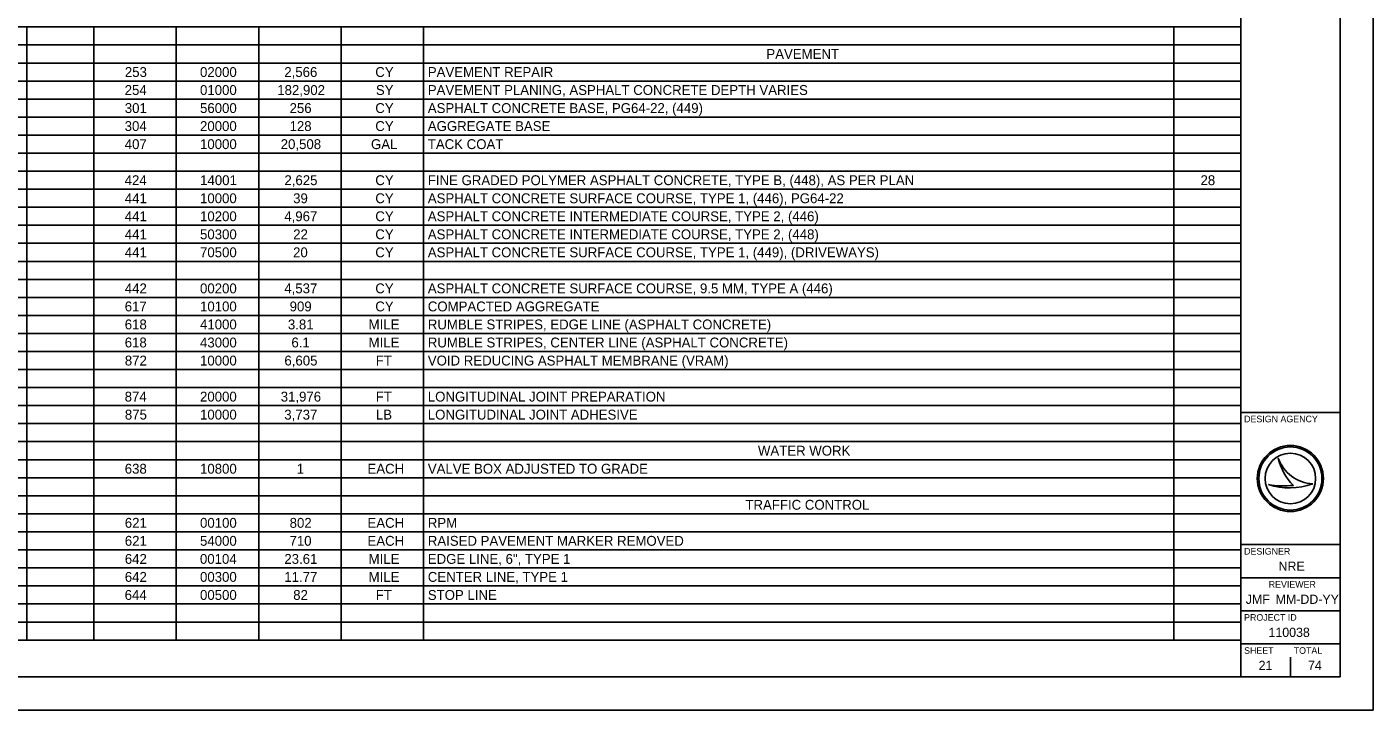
# Model space of a CAD drawing. Extents: x 0 to 34, y 0 to 22.
# Drawn here: x 13.65 to 34, y 0 to 10.33 of the extents above; entities that cross this region are included whole.
import ezdxf

# ---------------------------------------------------------------- set-up
doc = ezdxf.new("R2010")
doc.units = 0
for name, color, linetype in [('Default', 7, 'Continuous'), ('SH_Border', 7, 'Continuous'), ('SH_Cut_Line', 7, 'Continuous'), ('SH_Data', 7, 'Continuous')]:
    doc.layers.add(name, color=color, linetype=linetype)

msp = doc.modelspace()

# ---------------------------------------------------------------- linework, layer by layer
at = {"layer": 'Default'}
for p, q in [((12.636, 10.325), (13.648, 10.325)), ((13.648, 10.325), (32, 10.325)), ((13.648, 10.325), (13.648, 10.053)), ((14.66, 10.325), (14.66, 10.053)), ((15.906, 10.325), (15.906, 10.053)), ((17.152, 10.325), (17.152, 10.053)), ((18.398, 10.325), (18.398, 10.053)), ((19.644, 10.325), (19.644, 10.053)), ((30.988, 10.325), (30.988, 10.053)), ((32, 10.325), (32, 10.053)), ((12.636, 10.053), (13.648, 10.053)), ((13.648, 10.053), (32, 10.053)), ((13.648, 10.053), (13.648, 9.235)), ((14.66, 10.053), (14.66, 9.235)), ((15.906, 10.053), (15.906, 9.235)), ((17.152, 10.053), (17.152, 9.235)), ((18.398, 10.053), (18.398, 9.235)), ((19.644, 10.053), (19.644, 9.235)), ((30.988, 10.053), (30.988, 9.235)), ((32, 10.053), (32, 9.235)), ((12.636, 9.78), (13.648, 9.78)), ((13.648, 9.78), (32, 9.78)), ((12.636, 9.508), (13.648, 9.508)), ((13.648, 9.508), (32, 9.508)), ((12.636, 9.235), (13.648, 9.235)), ((13.648, 9.235), (32, 9.235)), ((13.648, 9.235), (13.648, 8.69)), ((14.66, 9.235), (14.66, 8.69)), ((15.906, 9.235), (15.906, 8.69)), ((17.152, 9.235), (17.152, 8.69)), ((18.398, 9.235), (18.398, 8.69)), ((19.644, 9.235), (19.644, 8.69)), ((30.988, 9.235), (30.988, 8.69)), ((32, 9.235), (32, 8.69)), ((12.636, 8.963), (13.648, 8.963)), ((13.648, 8.963), (32, 8.963)), ((12.636, 8.69), (13.648, 8.69)), ((13.648, 8.69), (32, 8.69)), ((13.648, 8.69), (13.648, 7.872)), ((14.66, 8.69), (14.66, 7.872)), ((15.906, 8.69), (15.906, 7.872)), ((17.152, 8.69), (17.152, 7.872)), ((18.398, 8.69), (18.398, 7.872)), ((19.644, 8.69), (19.644, 7.872)), ((30.988, 8.69), (30.988, 7.872)), ((32, 8.69), (32, 7.872)), ((12.636, 8.417), (13.648, 8.417)), ((13.648, 8.417), (32, 8.417)), ((12.636, 8.145), (13.648, 8.145)), ((13.648, 8.145), (32, 8.145)), ((12.636, 7.872), (13.648, 7.872)), ((13.648, 7.872), (32, 7.872)), ((13.648, 7.872), (13.648, 7.327)), ((14.66, 7.872), (14.66, 7.327)), ((15.906, 7.872), (15.906, 7.327)), ((17.152, 7.872), (17.152, 7.327)), ((18.398, 7.872), (18.398, 7.327)), ((19.644, 7.872), (19.644, 7.327)), ((30.988, 7.872), (30.988, 7.327)), ((32, 7.872), (32, 7.327)), ((12.636, 7.6), (13.648, 7.6)), ((13.648, 7.6), (32, 7.6)), ((12.636, 7.327), (13.648, 7.327)), ((13.648, 7.327), (32, 7.327)), ((13.648, 7.327), (13.648, 6.51)), ((14.66, 7.327), (14.66, 6.51)), ((15.906, 7.327), (15.906, 6.51)), ((17.152, 7.327), (17.152, 6.51)), ((18.398, 7.327), (18.398, 6.51)), ((19.644, 7.327), (19.644, 6.51)), ((30.988, 7.327), (30.988, 6.51)), ((32, 7.327), (32, 6.51)), ((12.636, 7.055), (13.648, 7.055)), ((13.648, 7.055), (32, 7.055)), ((12.636, 6.782), (13.648, 6.782)), ((13.648, 6.782), (32, 6.782)), ((12.636, 6.51), (13.648, 6.51)), ((13.648, 6.51), (32, 6.51)), ((13.648, 6.51), (13.648, 5.419)), ((14.66, 6.51), (14.66, 5.419)), ((15.906, 6.51), (15.906, 5.419)), ((17.152, 6.51), (17.152, 5.419)), ((18.398, 6.51), (18.398, 5.419)), ((19.644, 6.51), (19.644, 5.419)), ((30.988, 6.51), (30.988, 5.419)), ((32, 6.51), (32, 5.419)), ((12.636, 6.237), (13.648, 6.237)), ((13.648, 6.237), (32, 6.237)), ((12.636, 5.964), (13.648, 5.964)), ((13.648, 5.964), (32, 5.964)), ((12.636, 5.692), (13.648, 5.692)), ((13.648, 5.692), (32, 5.692)), ((12.636, 5.419), (13.648, 5.419)), ((13.648, 5.419), (32, 5.419)), ((13.648, 5.419), (13.648, 5.147)), ((14.66, 5.419), (14.66, 5.147)), ((15.906, 5.419), (15.906, 5.147)), ((17.152, 5.419), (17.152, 5.147)), ((18.398, 5.419), (18.398, 5.147)), ((19.644, 5.419), (19.644, 5.147)), ((30.988, 5.419), (30.988, 5.147)), ((32, 5.419), (32, 5.147)), ((12.636, 5.147), (13.648, 5.147)), ((13.648, 5.147), (32, 5.147)), ((13.648, 5.147), (13.648, 4.057)), ((14.66, 5.147), (14.66, 4.057)), ((15.906, 5.147), (15.906, 4.057)), ((17.152, 5.147), (17.152, 4.057)), ((18.398, 5.147), (18.398, 4.057)), ((19.644, 5.147), (19.644, 4.057)), ((30.988, 5.147), (30.988, 4.057)), ((32, 5.147), (32, 4.057)), ((12.636, 4.874), (13.648, 4.874)), ((13.648, 4.874), (32, 4.874)), ((12.636, 4.602), (13.648, 4.602)), ((13.648, 4.602), (32, 4.602)), ((12.636, 4.329), (13.648, 4.329)), ((13.648, 4.329), (32, 4.329)), ((12.636, 4.057), (13.648, 4.057)), ((13.648, 4.057), (32, 4.057)), ((13.648, 4.057), (13.648, 3.784)), ((14.66, 4.057), (14.66, 3.784)), ((15.906, 4.057), (15.906, 3.784)), ((17.152, 4.057), (17.152, 3.784)), ((18.398, 4.057), (18.398, 3.784)), ((19.644, 4.057), (19.644, 3.784)), ((30.988, 4.057), (30.988, 3.784)), ((32, 4.057), (32, 3.784)), ((12.636, 3.784), (13.648, 3.784)), ((13.648, 3.784), (32, 3.784)), ((13.648, 3.784), (13.648, 2.694)), ((14.66, 3.784), (14.66, 2.694)), ((15.906, 3.784), (15.906, 2.694)), ((17.152, 3.784), (17.152, 2.694)), ((18.398, 3.784), (18.398, 2.694)), ((19.644, 3.784), (19.644, 2.694)), ((30.988, 3.784), (30.988, 2.694)), ((32, 3.784), (32, 2.694)), ((12.636, 3.511), (13.648, 3.511)), ((13.648, 3.511), (32, 3.511)), ((12.636, 3.239), (13.648, 3.239)), ((13.648, 3.239), (32, 3.239)), ((12.636, 2.966), (13.648, 2.966)), ((13.648, 2.966), (32, 2.966)), ((12.636, 2.694), (13.648, 2.694)), ((13.648, 2.694), (32, 2.694)), ((13.648, 2.694), (13.648, 2.421)), ((14.66, 2.694), (14.66, 2.421)), ((15.906, 2.694), (15.906, 2.421)), ((17.152, 2.694), (17.152, 2.421)), ((18.398, 2.694), (18.398, 2.421)), ((19.644, 2.694), (19.644, 2.421)), ((30.988, 2.694), (30.988, 2.421)), ((32, 2.694), (32, 2.421)), ((12.636, 2.421), (13.648, 2.421)), ((13.648, 2.421), (32, 2.421)), ((13.648, 2.421), (13.648, 1.331)), ((14.66, 2.421), (14.66, 1.331)), ((15.906, 2.421), (15.906, 1.331)), ((17.152, 2.421), (17.152, 1.331)), ((18.398, 2.421), (18.398, 1.331)), ((19.644, 2.421), (19.644, 1.331)), ((30.988, 2.421), (30.988, 1.331)), ((32, 2.421), (32, 1.331)), ((12.636, 2.149), (13.648, 2.149)), ((13.648, 2.149), (32, 2.149)), ((12.636, 1.876), (13.648, 1.876)), ((13.648, 1.876), (32, 1.876)), ((12.636, 1.604), (13.648, 1.604)), ((13.648, 1.604), (32, 1.604)), ((12.636, 1.331), (13.648, 1.331)), ((13.648, 1.331), (32, 1.331)), ((13.648, 1.331), (13.648, 1.059)), ((14.66, 1.331), (14.66, 1.059)), ((15.906, 1.331), (15.906, 1.059)), ((17.152, 1.331), (17.152, 1.059)), ((18.398, 1.331), (18.398, 1.059)), ((19.644, 1.331), (19.644, 1.059)), ((30.988, 1.331), (30.988, 1.059)), ((32, 1.331), (32, 1.059)), ((12.636, 1.059), (13.648, 1.059)), ((13.648, 1.059), (32, 1.059))]:
    msp.add_line(p, q, dxfattribs=at)
at = {"layer": 'SH_Border'}
for p, q in [((32, 0.5), (32, 21.5)), ((32, 4.5), (33.5, 4.5)), ((32, 2.5), (33.5, 2.5)), ((32, 2), (33.5, 2)), ((32, 1.5), (33.5, 1.5)), ((32, 1), (33.5, 1))]:
    msp.add_line(p, q, dxfattribs=at)
msp.add_lwpolyline([(1.5, 21.5), (33.5, 21.5), (33.5, 0.5), (1.5, 0.5)], close=True, dxfattribs=at)
at = {"layer": 'SH_Cut_Line'}
msp.add_lwpolyline([(0, 0), (34, 0), (34, 22), (0, 22)], close=True, dxfattribs=at)
at = {"layer": 'SH_Data'}
for p, q in [((32.567, 3.81), (32.567, 3.81)), ((32.75, 3.5), (32.75, 3.5)), ((32.417, 3.41), (32.417, 3.41)), ((33.087, 3.419), (33.087, 3.419)), ((32.375, 0.675), (32.375, 0.675)), ((32.75, 0.5), (32.75, 0.8))]:
    msp.add_line(p, q, dxfattribs=at)
for radius in [0.5, 0.477, 0.477, 0.382]:
    msp.add_circle((32.75, 3.5), radius, dxfattribs=at)
for centre, radius, start, end in [((33.116, 3.998), 0.58, 198.9257, 198.9319), ((33.347, 3.97), 0.796, 191.6379, 191.6421), ((33.116, 3.998), 0.58, 198.9319, 267.1657), ((33.347, 3.97), 0.796, 191.6421, 226.0947), ((32.739, 4.37), 1.013, 251.4576, 290.0832), ((32.648, 4.654), 1.266, 259.4964, 259.4995), ((32.739, 4.37), 1.013, 251.4527, 251.4576), ((32.648, 4.654), 1.266, 259.4995, 276.6672)]:
    msp.add_arc(centre, radius, start, end, dxfattribs=at)

# ---------------------------------------------------------------- texts
at = {"layer": 'Default'}
for s, height, p in [('PAVEMENT', 0.1493, (24.828, 9.842)), ('253', 0.1493, (15.129, 9.569)), ('02000', 0.1493, (16.265, 9.569)), ('2,566', 0.1493, (17.539, 9.569)), ('CY', 0.1493, (18.915, 9.569)), ('PAVEMENT REPAIR', 0.14926, (19.709, 9.569)), ('254', 0.1493, (15.126, 9.297)), ('01000', 0.1493, (16.265, 9.297)), ('182,902', 0.1493, (17.433, 9.297)), ('SY', 0.1493, (18.924, 9.297)), ('PAVEMENT PLANING, ASPHALT CONCRETE DEPTH VARIES', 0.14926, (19.709, 9.297)), ('301', 0.1493, (15.128, 9.024)), ('56000', 0.1493, (16.265, 9.024)), ('256', 0.1493, (17.619, 9.024)), ('CY', 0.1493, (18.915, 9.024)), ('ASPHALT CONCRETE BASE, PG64-22, (449)', 0.14926, (19.709, 9.024)), ('304', 0.1493, (15.126, 8.752)), ('20000', 0.1493, (16.265, 8.752)), ('128', 0.1493, (17.619, 8.752)), ('CY', 0.1493, (18.915, 8.752)), ('AGGREGATE BASE', 0.14926, (19.709, 8.752)), ('407', 0.1493, (15.127, 8.479)), ('10000', 0.1493, (16.265, 8.479)), ('20,508', 0.1493, (17.485, 8.479)), ('GAL', 0.1493, (18.85, 8.479)), ('TACK COAT', 0.1493, (19.709, 8.479)), ('424', 0.1493, (15.126, 7.934)), ('14001', 0.1493, (16.267, 7.934)), ('2,625', 0.1493, (17.541, 7.934)), ('CY', 0.1493, (18.915, 7.934)), ('FINE GRADED POLYMER ASPHALT CONCRETE, TYPE B, (448), AS PER PLAN', 0.14926, (19.709, 7.934)), ('28', 0.1493, (31.391, 7.934)), ('441', 0.1493, (15.128, 7.661)), ('10000', 0.1493, (16.265, 7.661)), ('39', 0.1493, (17.673, 7.661)), ('CY', 0.1493, (18.915, 7.661)), ('ASPHALT CONCRETE SURFACE COURSE, TYPE 1, (446), PG64-22', 0.14926, (19.709, 7.661)), ('441', 0.1493, (15.128, 7.389)), ('10200', 0.1493, (16.265, 7.389)), ('4,967', 0.1493, (17.539, 7.389)), ('CY', 0.1493, (18.915, 7.389)), ('ASPHALT CONCRETE INTERMEDIATE COURSE, TYPE 2, (446)', 0.14926, (19.709, 7.389)), ('441', 0.1493, (15.128, 7.116)), ('50300', 0.1493, (16.265, 7.116)), ('22', 0.1493, (17.674, 7.116)), ('CY', 0.1493, (18.915, 7.116)), ('ASPHALT CONCRETE INTERMEDIATE COURSE, TYPE 2, (448)', 0.14926, (19.709, 7.116)), ('441', 0.1493, (15.128, 6.844)), ('70500', 0.1493, (16.265, 6.844)), ('20', 0.1493, (17.672, 6.844)), ('CY', 0.1493, (18.915, 6.844)), ('ASPHALT CONCRETE SURFACE COURSE, TYPE 1, (449), (DRIVEWAYS)', 0.14926, (19.709, 6.844)), ('442', 0.1493, (15.128, 6.299)), ('00200', 0.1493, (16.265, 6.299)), ('4,537', 0.1493, (17.539, 6.299)), ('CY', 0.1493, (18.915, 6.299)), ('ASPHALT CONCRETE SURFACE COURSE, 9.5 MM, TYPE A (446)', 0.14926, (19.709, 6.299)), ('617', 0.1493, (15.127, 6.026)), ('10100', 0.1493, (16.265, 6.026)), ('909', 0.1493, (17.62, 6.026)), ('CY', 0.1493, (18.915, 6.026)), ('COMPACTED AGGREGATE', 0.14926, (19.709, 6.026)), ('618', 0.1493, (15.127, 5.754)), ('41000', 0.1493, (16.265, 5.754)), ('3.81', 0.1493, (17.594, 5.754)), ('MILE', 0.1493, (18.814, 5.754)), ('RUMBLE STRIPES, EDGE LINE (ASPHALT CONCRETE)', 0.14926, (19.709, 5.754)), ('618', 0.1493, (15.127, 5.481)), ('43000', 0.1493, (16.265, 5.481)), ('6.1', 0.1493, (17.647, 5.481)), ('MILE', 0.1493, (18.814, 5.481)), ('RUMBLE STRIPES, CENTER LINE (ASPHALT CONCRETE)', 0.14926, (19.709, 5.481)), ('872', 0.1493, (15.128, 5.208)), ('10000', 0.1493, (16.265, 5.208)), ('6,605', 0.1493, (17.541, 5.208)), ('FT', 0.1493, (18.922, 5.208)), ('VOID REDUCING ASPHALT MEMBRANE (VRAM)', 0.14926, (19.709, 5.208)), ('874', 0.1493, (15.126, 4.663)), ('20000', 0.1493, (16.265, 4.663)), ('31,976', 0.1493, (17.485, 4.663)), ('FT', 0.1493, (18.922, 4.663)), ('LONGITUDINAL JOINT PREPARATION', 0.14926, (19.709, 4.663)), ('875', 0.1493, (15.129, 4.391)), ('10000', 0.1493, (16.265, 4.391)), ('3,737', 0.1493, (17.539, 4.391)), ('LB', 0.1493, (18.924, 4.391)), ('LONGITUDINAL JOINT ADHESIVE', 0.14926, (19.709, 4.391)), ('WATER WORK', 0.1493, (24.7, 3.846)), ('638', 0.1493, (15.127, 3.573)), ('10800', 0.1493, (16.265, 3.573)), ('1', 0.149, (17.727, 3.573)), ('EACH', 0.1493, (18.797, 3.573)), ('VALVE BOX ADJUSTED TO GRADE', 0.14926, (19.709, 3.573)), ('TRAFFIC CONTROL', 0.14926, (24.511, 3.028)), ('621', 0.1493, (15.128, 2.755)), ('00100', 0.1493, (16.265, 2.755)), ('802', 0.1493, (17.62, 2.755)), ('EACH', 0.1493, (18.797, 2.755)), ('RPM', 0.1493, (19.709, 2.755)), ('621', 0.1493, (15.128, 2.483)), ('54000', 0.1493, (16.265, 2.483)), ('710', 0.1493, (17.618, 2.483)), ('EACH', 0.1493, (18.797, 2.483)), ('RAISED PAVEMENT MARKER REMOVED', 0.14926, (19.709, 2.483)), ('642', 0.1493, (15.128, 2.21)), ('00104', 0.1493, (16.264, 2.21)), ('23.61', 0.1493, (17.54, 2.21)), ('MILE', 0.1493, (18.814, 2.21)), ('EDGE LINE, 6", TYPE 1', 0.14926, (19.709, 2.21)), ('642', 0.1493, (15.128, 1.938)), ('00300', 0.1493, (16.265, 1.938)), ('11.77', 0.1493, (17.539, 1.938)), ('MILE', 0.1493, (18.814, 1.938)), ('CENTER LINE, TYPE 1', 0.14926, (19.709, 1.938)), ('644', 0.1493, (15.126, 1.665)), ('00500', 0.1493, (16.265, 1.665)), ('82', 0.1493, (17.674, 1.665)), ('FT', 0.1493, (18.922, 1.665)), ('STOP LINE', 0.1493, (19.709, 1.665))]:
    msp.add_text(s, height=height, dxfattribs=at).set_placement(p)
at = {"layer": 'SH_Data'}
for s, height, p in [('DESIGN AGENCY', 0.1, (32.05, 4.35)), ('DESIGNER', 0.1, (32.05, 2.35)), ('NRE', 0.14, (32.571, 2.105)), ('REVIEWER', 0.1, (32.422, 1.85)), ('JMF', 0.14, (32.075, 1.605)), ('MM-DD-YY', 0.14, (32.527, 1.605)), ('PROJECT ID', 0.1, (32.05, 1.35)), ('110038', 0.14, (32.419, 1.105)), ('SHEET', 0.1, (32.05, 0.85)), ('TOTAL', 0.1, (32.8, 0.85)), ('21', 0.14, (32.269, 0.605)), ('74', 0.14, (33.016, 0.605))]:
    msp.add_text(s, height=height, dxfattribs=at).set_placement(p)

doc.saveas('drawing.dxf')
